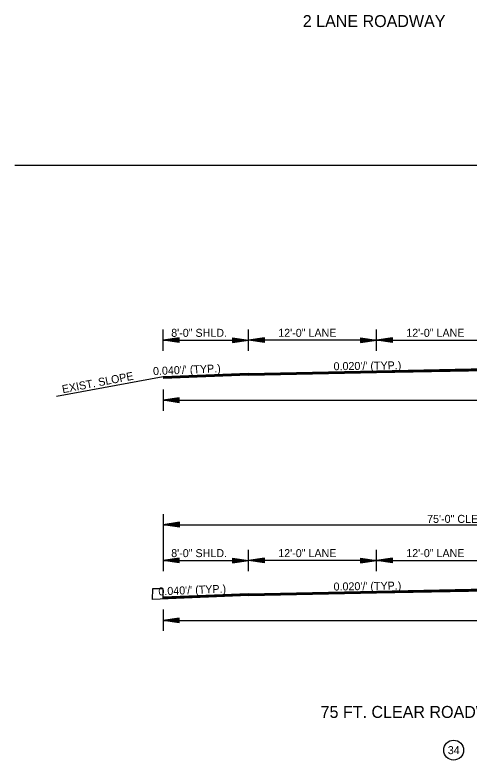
# Model space of a CAD drawing. Extents: x 545241 to 1930787, y -1971772 to 596640.
# Drawn here: x 546745 to 547171, y -1963944 to -1963245 of the extents above; entities that cross this region are included whole.
import ezdxf

# ---------------------------------------------------------------- set-up
doc = ezdxf.new("R2010")
doc.units = 0
doc.layers.add('R_Border', color=7, linetype='Continuous')
doc.layers.add('R_Draft', color=7, linetype='Continuous')

msp = doc.modelspace()

# ---------------------------------------------------------------- linework, layer by layer
at = {"layer": 'R_Border'}
for p, q in [((546745.07, -1963386.13), (547773.02, -1963386.13)), ((546884.04, -1963550.29), (546964.04, -1963550.29)), ((546884.04, -1963756.68), (546964.04, -1963756.68)), ((546873.88, -1963783.08), (546873.86, -1963793.07)), ((546884.04, -1963783.08), (546873.88, -1963783.08)), ((546884.04, -1963792.49), (546884.04, -1963783.08))]:
    msp.add_line(p, q, dxfattribs=at)
msp.add_circle((547156.23, -1963934.33), 9.34, dxfattribs=at)
at = {"layer": 'R_Draft'}
for p, q in [((546884.04, -1963560.29), (546884.04, -1963540.29)), ((546964.04, -1963560.29), (546964.04, -1963540.39)), ((547084.04, -1963560.29), (547084.04, -1963540.39)), ((546899.04, -1963548.04), (546884.04, -1963550.29)), ((546899.04, -1963552.54), (546884.04, -1963550.29)), ((546899.04, -1963548.41), (546886.55, -1963550.29)), ((546899.04, -1963552.16), (546886.55, -1963550.29)), ((546899.04, -1963548.79), (546889.13, -1963550.29)), ((546899.04, -1963551.78), (546889.13, -1963550.29)), ((546899.04, -1963549.17), (546891.63, -1963550.29)), ((546899.04, -1963551.4), (546891.63, -1963550.29)), ((546899.04, -1963549.55), (546894.17, -1963550.29)), ((546899.04, -1963551.01), (546894.17, -1963550.29)), ((546899.04, -1963549.93), (546896.67, -1963550.29)), ((546899.04, -1963550.64), (546896.67, -1963550.29)), ((546899.04, -1963552.54), (546899.04, -1963548.04)), ((546949.04, -1963548.04), (546964.04, -1963550.29)), ((546949.04, -1963548.04), (546949.04, -1963552.54)), ((546949.04, -1963548.41), (546961.54, -1963550.29)), ((546949.04, -1963548.79), (546958.96, -1963550.29)), ((546949.04, -1963549.17), (546956.46, -1963550.29)), ((546949.04, -1963549.56), (546953.92, -1963550.29)), ((546949.04, -1963549.93), (546951.41, -1963550.29)), ((546949.04, -1963552.54), (546964.04, -1963550.29)), ((546949.04, -1963551.02), (546953.92, -1963550.29)), ((546949.04, -1963551.78), (546958.96, -1963550.29)), ((546949.04, -1963552.16), (546961.54, -1963550.29)), ((546949.04, -1963551.4), (546956.46, -1963550.29)), ((546949.04, -1963550.64), (546951.41, -1963550.29)), ((546979.04, -1963548.04), (546964.04, -1963550.29)), ((547084.04, -1963550.29), (546964.04, -1963550.29)), ((546979.04, -1963552.54), (546964.04, -1963550.29)), ((546979.04, -1963548.41), (546966.55, -1963550.29)), ((546979.04, -1963552.16), (546966.55, -1963550.29)), ((546979.04, -1963548.79), (546969.13, -1963550.29)), ((546979.04, -1963551.78), (546969.13, -1963550.29)), ((546979.04, -1963549.17), (546971.63, -1963550.29)), ((546979.04, -1963551.4), (546971.63, -1963550.29)), ((546979.04, -1963549.55), (546974.17, -1963550.29)), ((546979.04, -1963551.01), (546974.17, -1963550.29)), ((546979.04, -1963549.93), (546976.67, -1963550.29)), ((546979.04, -1963550.64), (546976.67, -1963550.29)), ((546979.04, -1963552.54), (546979.04, -1963548.04)), ((547069.04, -1963548.04), (547084.04, -1963550.29)), ((547069.04, -1963548.04), (547069.04, -1963552.54)), ((547069.04, -1963548.41), (547081.54, -1963550.29)), ((547069.04, -1963548.79), (547078.96, -1963550.29)), ((547069.04, -1963549.17), (547076.46, -1963550.29)), ((547069.04, -1963549.56), (547073.92, -1963550.29)), ((547069.04, -1963549.93), (547071.41, -1963550.29)), ((547069.04, -1963552.54), (547084.04, -1963550.29)), ((547069.04, -1963551.02), (547073.92, -1963550.29)), ((547069.04, -1963551.78), (547078.96, -1963550.29)), ((547069.04, -1963552.16), (547081.54, -1963550.29)), ((547069.04, -1963551.4), (547076.46, -1963550.29)), ((547069.04, -1963550.64), (547071.41, -1963550.29)), ((547099.04, -1963548.04), (547084.04, -1963550.29)), ((547084.04, -1963550.29), (547204.04, -1963550.29)), ((547099.04, -1963552.54), (547084.04, -1963550.29)), ((547099.04, -1963548.41), (547086.55, -1963550.29)), ((547099.04, -1963552.16), (547086.55, -1963550.29)), ((547099.04, -1963548.79), (547089.13, -1963550.29)), ((547099.04, -1963551.78), (547089.13, -1963550.29)), ((547099.04, -1963549.17), (547091.63, -1963550.29)), ((547099.04, -1963551.4), (547091.63, -1963550.29)), ((547099.04, -1963549.55), (547094.17, -1963550.29)), ((547099.04, -1963551.01), (547094.17, -1963550.29)), ((547099.04, -1963549.93), (547096.67, -1963550.29)), ((547099.04, -1963550.64), (547096.67, -1963550.29)), ((547099.04, -1963552.54), (547099.04, -1963548.04)), ((546964.04, -1963581.39), (547084.04, -1963578.99)), ((546964.04, -1963581.69), (547084.04, -1963579.29)), ((546964.04, -1963581.99), (547084.04, -1963579.59)), ((546964.04, -1963582.29), (547084.04, -1963579.89)), ((546964.04, -1963582.59), (547084.04, -1963580.19)), ((546964.04, -1963582.89), (547084.04, -1963580.49)), ((546964.04, -1963583.06), (547084.04, -1963580.66)), ((547084.04, -1963578.99), (547204.04, -1963576.59)), ((547084.04, -1963579.29), (547204.04, -1963576.89)), ((547084.04, -1963579.59), (547204.04, -1963577.19)), ((547084.04, -1963579.89), (547204.04, -1963577.49)), ((547084.04, -1963580.19), (547204.04, -1963577.79)), ((547084.04, -1963580.49), (547204.04, -1963578.09)), ((547084.04, -1963580.66), (547204.04, -1963578.26)), ((546884.04, -1963584.59), (546783.98, -1963602.97)), ((546964.04, -1963581.39), (546884.04, -1963584.59)), ((546964.05, -1963581.69), (546884.04, -1963584.89)), ((546964.06, -1963581.99), (546884.04, -1963585.19)), ((546964.07, -1963582.29), (546884.04, -1963585.49)), ((546964.08, -1963582.59), (546884.04, -1963585.79)), ((546964.09, -1963582.89), (546884.04, -1963586.09)), ((546964.09, -1963583.06), (546884.04, -1963586.26)), ((546914.04, -1963583.39), (546914.04, -1963585.06)), ((546884.04, -1963596.3), (546884.04, -1963616.3)), ((546899.03, -1963604.3), (546884.03, -1963606.55)), ((546899.03, -1963608.8), (546884.03, -1963606.55)), ((546884.04, -1963606.55), (547634.04, -1963606.55)), ((546899.03, -1963604.68), (546886.53, -1963606.55)), ((546899.03, -1963608.43), (546886.53, -1963606.55)), ((546899.03, -1963605.06), (546889.11, -1963606.55)), ((546899.03, -1963608.04), (546889.11, -1963606.55)), ((546899.03, -1963605.43), (546891.61, -1963606.55)), ((546899.03, -1963607.67), (546891.61, -1963606.55)), ((546899.03, -1963605.82), (546894.15, -1963606.55)), ((546899.03, -1963607.28), (546894.15, -1963606.55)), ((546899.03, -1963606.2), (546896.66, -1963606.55)), ((546899.03, -1963606.9), (546896.66, -1963606.55)), ((546899.03, -1963608.8), (546899.03, -1963604.3)), ((546884.04, -1963713.15), (546884.04, -1963766.68)), ((546884.04, -1963723.15), (547634.04, -1963723.15)), ((546899.17, -1963720.9), (546884.17, -1963723.15)), ((546899.17, -1963725.4), (546884.17, -1963723.15)), ((546899.17, -1963721.27), (546886.68, -1963723.15)), ((546899.17, -1963725.02), (546886.68, -1963723.15)), ((546899.17, -1963721.65), (546889.26, -1963723.15)), ((546899.17, -1963724.64), (546889.26, -1963723.15)), ((546899.17, -1963722.03), (546891.75, -1963723.15)), ((546899.17, -1963724.26), (546891.75, -1963723.15)), ((546899.17, -1963722.41), (546894.3, -1963723.15)), ((546899.17, -1963723.87), (546894.3, -1963723.15)), ((546899.17, -1963722.79), (546896.8, -1963723.15)), ((546899.17, -1963723.5), (546896.8, -1963723.15)), ((546899.17, -1963725.4), (546899.17, -1963720.9)), ((546964.04, -1963766.68), (546964.04, -1963746.79)), ((547084.04, -1963766.68), (547084.04, -1963746.79)), ((546899.04, -1963754.43), (546884.04, -1963756.68)), ((546899.04, -1963754.81), (546886.55, -1963756.68)), ((546899.04, -1963755.19), (546889.13, -1963756.68)), ((546899.04, -1963755.57), (546891.63, -1963756.68)), ((546899.04, -1963758.93), (546899.04, -1963754.43)), ((546949.04, -1963754.43), (546964.04, -1963756.68)), ((546949.04, -1963754.43), (546949.04, -1963758.93)), ((546949.04, -1963754.81), (546961.54, -1963756.68)), ((546949.04, -1963755.19), (546958.96, -1963756.68)), ((546949.04, -1963755.57), (546956.46, -1963756.68)), ((546979.04, -1963754.43), (546964.04, -1963756.68)), ((546979.04, -1963754.81), (546966.55, -1963756.68)), ((546979.04, -1963755.19), (546969.13, -1963756.68)), ((546979.04, -1963755.57), (546971.63, -1963756.68)), ((546979.04, -1963758.93), (546979.04, -1963754.43)), ((547069.04, -1963754.43), (547084.04, -1963756.68)), ((547069.04, -1963754.43), (547069.04, -1963758.93)), ((547069.04, -1963754.81), (547081.54, -1963756.68)), ((547069.04, -1963755.19), (547078.96, -1963756.68)), ((547069.04, -1963755.57), (547076.46, -1963756.68)), ((547099.04, -1963754.43), (547084.04, -1963756.68)), ((547099.04, -1963754.81), (547086.55, -1963756.68)), ((547099.04, -1963755.19), (547089.13, -1963756.68)), ((547099.04, -1963755.57), (547091.63, -1963756.68)), ((547099.04, -1963758.93), (547099.04, -1963754.43)), ((546899.04, -1963758.93), (546884.04, -1963756.68)), ((546899.04, -1963758.56), (546886.55, -1963756.68)), ((546899.04, -1963758.18), (546889.13, -1963756.68)), ((546899.04, -1963757.8), (546891.63, -1963756.68)), ((546899.04, -1963755.95), (546894.17, -1963756.68)), ((546899.04, -1963757.41), (546894.17, -1963756.68)), ((546899.04, -1963756.33), (546896.67, -1963756.68)), ((546899.04, -1963757.04), (546896.67, -1963756.68)), ((546949.04, -1963755.96), (546953.92, -1963756.68)), ((546949.04, -1963756.33), (546951.41, -1963756.68)), ((546949.04, -1963758.93), (546964.04, -1963756.68)), ((546949.04, -1963757.42), (546953.92, -1963756.68)), ((546949.04, -1963758.18), (546958.96, -1963756.68)), ((546949.04, -1963758.56), (546961.54, -1963756.68)), ((546949.04, -1963757.8), (546956.46, -1963756.68)), ((546949.04, -1963757.04), (546951.41, -1963756.68)), ((547084.04, -1963756.68), (546964.04, -1963756.68)), ((546979.04, -1963758.93), (546964.04, -1963756.68)), ((546979.04, -1963758.56), (546966.55, -1963756.68)), ((546979.04, -1963758.18), (546969.13, -1963756.68)), ((546979.04, -1963757.8), (546971.63, -1963756.68)), ((546979.04, -1963755.95), (546974.17, -1963756.68)), ((546979.04, -1963757.41), (546974.17, -1963756.68)), ((546979.04, -1963756.33), (546976.67, -1963756.68)), ((546979.04, -1963757.04), (546976.67, -1963756.68)), ((547069.04, -1963755.96), (547073.92, -1963756.68)), ((547069.04, -1963756.33), (547071.41, -1963756.68)), ((547069.04, -1963758.93), (547084.04, -1963756.68)), ((547069.04, -1963757.42), (547073.92, -1963756.68)), ((547069.04, -1963758.18), (547078.96, -1963756.68)), ((547069.04, -1963758.56), (547081.54, -1963756.68)), ((547069.04, -1963757.8), (547076.46, -1963756.68)), ((547069.04, -1963757.04), (547071.41, -1963756.68)), ((547084.04, -1963756.68), (547204.04, -1963756.68)), ((547099.04, -1963758.93), (547084.04, -1963756.68)), ((547099.04, -1963758.56), (547086.55, -1963756.68)), ((547099.04, -1963758.18), (547089.13, -1963756.68)), ((547099.04, -1963757.8), (547091.63, -1963756.68)), ((547099.04, -1963755.95), (547094.17, -1963756.68)), ((547099.04, -1963757.41), (547094.17, -1963756.68)), ((547099.04, -1963756.33), (547096.67, -1963756.68)), ((547099.04, -1963757.04), (547096.67, -1963756.68)), ((547084.04, -1963785.39), (547204.04, -1963782.99)), ((547084.04, -1963785.69), (547204.04, -1963783.29)), ((546964.09, -1963789.46), (546873.86, -1963793.07)), ((546964.04, -1963787.79), (546884.04, -1963790.99)), ((546964.05, -1963788.09), (546884.04, -1963791.29)), ((546964.06, -1963788.39), (546884.04, -1963791.59)), ((546964.07, -1963788.69), (546884.04, -1963791.89)), ((546964.08, -1963788.99), (546884.04, -1963792.19)), ((546964.09, -1963789.29), (546884.04, -1963792.49)), ((546914.04, -1963789.79), (546914.04, -1963791.46)), ((546964.04, -1963787.79), (547084.04, -1963785.39)), ((546964.04, -1963788.09), (547084.04, -1963785.69)), ((546964.04, -1963788.39), (547084.04, -1963785.99)), ((546964.04, -1963788.69), (547084.04, -1963786.29)), ((546964.04, -1963788.99), (547084.04, -1963786.59)), ((546964.04, -1963789.29), (547084.04, -1963786.89)), ((546964.04, -1963789.46), (547084.04, -1963787.06)), ((547084.04, -1963785.99), (547204.04, -1963783.59)), ((547084.04, -1963786.29), (547204.04, -1963783.89)), ((547084.04, -1963786.59), (547204.04, -1963784.19)), ((547084.04, -1963786.89), (547204.04, -1963784.49)), ((547084.04, -1963787.06), (547204.04, -1963784.66)), ((546884.04, -1963802.7), (546884.04, -1963822.7)), ((546899.03, -1963810.7), (546884.03, -1963812.95)), ((546899.03, -1963811.07), (546886.53, -1963812.95)), ((546899.03, -1963811.45), (546889.11, -1963812.95)), ((546899.03, -1963815.2), (546899.03, -1963810.7)), ((546899.03, -1963815.2), (546884.03, -1963812.95)), ((546884.04, -1963812.95), (547634.04, -1963812.95)), ((546899.03, -1963814.82), (546886.53, -1963812.95)), ((546899.03, -1963814.44), (546889.11, -1963812.95)), ((546899.03, -1963811.83), (546891.61, -1963812.95)), ((546899.03, -1963814.06), (546891.61, -1963812.95)), ((546899.03, -1963812.21), (546894.15, -1963812.95)), ((546899.03, -1963813.67), (546894.15, -1963812.95)), ((546899.03, -1963812.59), (546896.66, -1963812.95)), ((546899.03, -1963813.3), (546896.66, -1963812.95))]:
    msp.add_line(p, q, dxfattribs=at)

# ---------------------------------------------------------------- texts
for s, height, p in [('2 LANE ROADWAY', 11.25, (547014.84, -1963256.91)), ('8\'-0" SHLD.', 7.5, (546891.56, -1963547.11)), ('12\'-0" LANE', 7.5, (546991.86, -1963547.11)), ('12\'-0" LANE', 7.5, (547111.86, -1963547.11)), ('75\'-0" CLEAR ROADWAY (POLYMER OVERLAY)', 7.5, (547131.37, -1963721.43)), ('8\'-0" SHLD.', 7.5, (546891.56, -1963753.51)), ('12\'-0" LANE', 7.5, (546991.86, -1963753.51)), ('12\'-0" LANE', 7.5, (547111.86, -1963753.51)), ('75 FT. CLEAR ROADWAY BRIDGE - POLYMER OVERLAY', 11.25, (547031.56, -1963904.17)), ('34', 7.5, (547150.74, -1963938.08))]:
    msp.add_text(s, height=height, dxfattribs=at).set_placement(p)
for s, rotation, p in [("  0.040'/' (TYP.)", 2.44797, (546869.1, -1963583.24)), ("0.020'/' (TYP.)", 0.87191, (547043.77, -1963578.46)), ('EXIST. SLOPE', 10.88286, (546789.96, -1963599.99)), ("0.020'/' (TYP.)", 0.87191, (547043.77, -1963784.86)), ("  0.040'/' (TYP.)", 2.44797, (546874.14, -1963789.64))]:
    msp.add_text(s, height=7.5, rotation=rotation, dxfattribs=at).set_placement(p)

doc.saveas('drawing.dxf')
